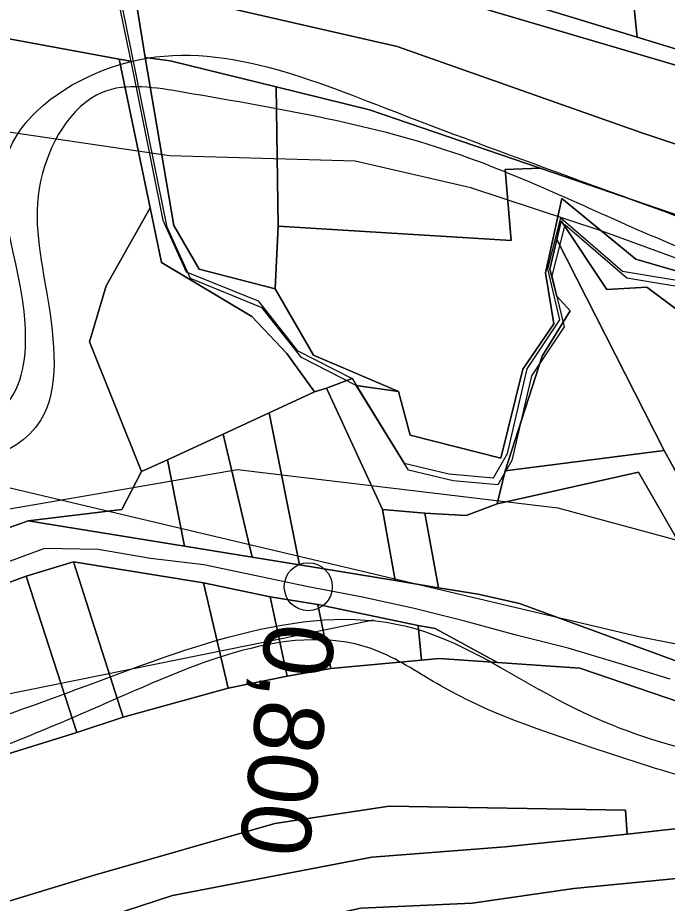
# Model space of a CAD drawing. Extents: x -510989 to -501240, y -1184665 to -1176098.
# Drawn here: x -503968.4 to -503846.8, y -1180716 to -1180550.1 of the extents above; entities that cross this region are included whole.
import ezdxf

# ---------------------------------------------------------------- set-up
doc = ezdxf.new("R2010")
doc.units = 0
for name, color, linetype in [('NAVRH_revitalizace_toku', 7, 'Continuous'), ('ostatni_plocha_x_draha', 7, 'Continuous'), ('ostatni_plocha_x_ostatni_komunikace', 7, 'Continuous'), ('ostatni_plocha_x_silnice', 7, 'Continuous'), ('popis', 7, 'Continuous'), ('STAV_zaplavove_uzemi', 7, 'Continuous'), ('trasovani_toku', 7, 'Continuous'), ('trvaly_travni_porost', 7, 'Continuous'), ('vodni_plocha_x_vodni_tok_v_koryt_prir_n_upr', 7, 'Continuous'), ('vrstevnice_02', 7, 'Continuous')]:
    doc.layers.add(name, color=color, linetype=linetype)

msp = doc.modelspace()

# ---------------------------------------------------------------- linework, layer by layer
at = {"layer": 'NAVRH_revitalizace_toku'}
for points in [[(-503969.95, -1180642.09), (-503927.27, -1180634.75), (-503867.26, -1180641.91), (-503821.69, -1180654.25), (-503752.11, -1180673.74)], [(-503901.78, -1180662.94), (-503999.13, -1180682.69), (-504068.01, -1180696.67), (-504089.48, -1180705.16), (-504129.41, -1180745.09), (-504183.13, -1180792.56)]]:
    msp.add_lwpolyline(points, dxfattribs=at)
at = {"layer": 'ostatni_plocha_x_draha'}
for points in [[(-504050.38, -1180529.2), (-504011.3, -1180526.7), (-503991.91, -1180525.26), (-503972.65, -1180526.94), (-503942.7, -1180531.97), (-503920.4, -1180536.44), (-503878.69, -1180549.11), (-503842.28, -1180559.88), (-503797.62, -1180573.3), (-503768.92, -1180582.78), (-503755.03, -1180588.3), (-503740.5, -1180595.42), (-503728.04, -1180603.41), (-503696.54, -1180625.52), (-503684.47, -1180634.75), (-503671.84, -1180646.84), (-503660.86, -1180660.05), (-503645.78, -1180680.44), (-503636.8, -1180694.49), (-503624.93, -1180717.25)], [(-503536.64, -1180850.18), (-503560.57, -1180820.77), (-503579.71, -1180795.62), (-503597.29, -1180777.84), (-503641.82, -1180728.5), (-503675.8, -1180687.66), (-503699.02, -1180661.49), (-503714.51, -1180645.55), (-503771.73, -1180604.31), (-503793.07, -1180592.97), (-503820.15, -1180582.16), (-503851.54, -1180571.67), (-503897.34, -1180555.49), (-503936.67, -1180546.45), (-503962.9, -1180542.96), (-503983.6, -1180531.11), (-503992.96, -1180529.75), (-504016.96, -1180533.2), (-504032.06, -1180536.14), (-504051.35, -1180540.4)], [(-504050.53, -1180715.17), (-503994.39, -1180690.6), (-503992.99, -1180695.12), (-503985.88, -1180692.95), (-503973.84, -1180689.11), (-503957.35, -1180683.97), (-503948.66, -1180681.12), (-503928.99, -1180675.68), (-503917.92, -1180673.46), (-503909.8, -1180672), (-503892.82, -1180670.42), (-503889.47, -1180670.16), (-503878.59, -1180670.9), (-503863.19, -1180671.95), (-503822.35, -1180685.85), (-503787.22, -1180684.15), (-503784.06, -1180691.38), (-503775.83, -1180695.17), (-503729.09, -1180703.71), (-503708.13, -1180713.81), (-503705.69, -1180714.15), (-503707.85, -1180720.08)], [(-503734.33, -1180721.65), (-503751.58, -1180714.96), (-503794.99, -1180714.3), (-503808.49, -1180705.28), (-503817.5, -1180698.91), (-503854.29, -1180703), (-503854.59, -1180698.53), (-503898.88, -1180697.77), (-503920.25, -1180701.03), (-503954.25, -1180710.8), (-503989.35, -1180721.46)]]:
    msp.add_lwpolyline(points, dxfattribs=at)
at = {"layer": 'ostatni_plocha_x_ostatni_komunikace'}
for points in [[(-504051.14, -1180525.96), (-504032.16, -1180524.67), (-504012.08, -1180523.31), (-503992.58, -1180522.08), (-503984.03, -1180522.66), (-503971.77, -1180523.59), (-503964.41, -1180524.89), (-503942.14, -1180528.82), (-503919.43, -1180533.57), (-503877.43, -1180546.1), (-503852.44, -1180553.76), (-503841.4, -1180557.14), (-503807.92, -1180566.86), (-503796.47, -1180570.18), (-503772.8, -1180577.92), (-503767.53, -1180579.65), (-503754.07, -1180585.16), (-503744.07, -1180590.17), (-503738.37, -1180593.05), (-503724.98, -1180601.86)], [(-503624.93, -1180717.25), (-503636.8, -1180694.49), (-503645.78, -1180680.44), (-503660.86, -1180660.05), (-503671.84, -1180646.84), (-503684.47, -1180634.75), (-503696.54, -1180625.52), (-503728.04, -1180603.41), (-503740.5, -1180595.42), (-503755.03, -1180588.3), (-503768.92, -1180582.78), (-503797.62, -1180573.3), (-503842.28, -1180559.88), (-503878.69, -1180549.11), (-503920.4, -1180536.44), (-503942.7, -1180531.97), (-503972.65, -1180526.94), (-503991.91, -1180525.26), (-504011.3, -1180526.7), (-504050.38, -1180529.2)]]:
    msp.add_lwpolyline(points, dxfattribs=at)
at = {"layer": 'ostatni_plocha_x_silnice'}
for points in [[(-504072.24, -1180546.98), (-504010.25, -1180539.68), (-503958.29, -1180544.03), (-503949.49, -1180547.17), (-503947.96, -1180554.73), (-503947.24, -1180558.25), (-503949.39, -1180557.86), (-503956.84, -1180556.49), (-503978.56, -1180552.5), (-503985.02, -1180552.37), (-504002.84, -1180552.02), (-504013.31, -1180551.82), (-504017.65, -1180552.14), (-504049.58, -1180554.46)], [(-503723.72, -1180656.77), (-503750.38, -1180635.24), (-503779.78, -1180615.05), (-503800.58, -1180604.27), (-503827.69, -1180593), (-503835.46, -1180590.34), (-503870.6, -1180578.32), (-503902.52, -1180567.39), (-503920.01, -1180563.08), (-503939.86, -1180558.18), (-503944.5, -1180557.55), (-503945.09, -1180554.04), (-503946.18, -1180547.54), (-503951.51, -1180546.09), (-503962.9, -1180542.96), (-503936.67, -1180546.45), (-503897.34, -1180555.49), (-503851.54, -1180571.67), (-503820.15, -1180582.16), (-503793.07, -1180592.97), (-503771.73, -1180604.31), (-503714.51, -1180645.55)]]:
    msp.add_lwpolyline(points, dxfattribs=at)
at = {"layer": 'popis'}
msp.add_lwpolyline([(-503840.45, -1180601.19), (-503854.39, -1180598.91), (-503865.95, -1180588.91), (-503868.39, -1180598.43), (-503866.08, -1180608.02), (-503872.22, -1180617.17), (-503875.89, -1180633.02), (-503878.53, -1180637.62), (-503886.9, -1180636.85), (-503895.25, -1180634.84), (-503905.01, -1180619), (-503915.26, -1180613.73), (-503922.6, -1180604.43), (-503936.06, -1180598.98), (-503940.41, -1180589.33), (-503948.71, -1180548.45), (-503964.98, -1180543.24), (-503986.95, -1180532.09), (-504014.98, -1180533.71), (-504031.14, -1180537.19), (-504050.39, -1180541.83)], dxfattribs=at)
at = {"layer": 'STAV_zaplavove_uzemi'}
for points in [[(-504540.1, -1180857.4), (-504577.6, -1180869.9), (-504578.56, -1180860.28), (-504550.67, -1180843.94), (-504523.75, -1180837.2), (-504478.55, -1180823.74), (-504444.9, -1180804.51), (-504446.82, -1180793.93), (-504446.82, -1180779.51), (-504445.86, -1180755.47), (-504441.05, -1180745.85), (-504426.63, -1180754.51), (-504417.97, -1180766.04), (-504413.17, -1180777.58), (-504398.74, -1180788.16), (-504367.97, -1180786.24), (-504329.51, -1180770.85), (-504283.35, -1180754.51), (-504262.2, -1180724.7), (-504238.16, -1180694.89), (-504218.92, -1180663.15), (-504185.27, -1180631.42), (-504166.04, -1180606.42), (-504143.92, -1180591.03), (-504113.15, -1180572.76), (-504085.26, -1180570.84), (-504067.95, -1180564.11), (-504042.95, -1180584.3), (-504041.99, -1180609.3), (-504034.29, -1180620.84), (-504019.87, -1180632.38), (-503985.25, -1180627.57), (-503970.83, -1180622.77), (-503966.98, -1180607.38), (-503969.87, -1180574.69), (-503950.64, -1180559.3), (-503899.67, -1180566.99), (-503832.36, -1180592), (-503773.38, -1180619.38), (-503737.54, -1180645.61), (-503699.95, -1180679.7), (-503682.47, -1180704.18), (-503669.35, -1180719.04), (-503664.11, -1180725.16), (-503685.09, -1180722.54), (-503689.46, -1180721.66), (-503691.21, -1180741.77), (-503665.86, -1180776.74), (-503654.49, -1180807.33), (-503622.15, -1180837.93), (-503605.54, -1180857.16), (-503581.94, -1180873.77), (-503569.7, -1180887.76), (-503551.34, -1180899.12), (-503533.86, -1180905.24), (-503519.87, -1180914.86), (-503521.62, -1180886.01), (-503509.38, -1180869.4), (-503486.65, -1180862.41), (-503463.92, -1180863.28), (-503442.94, -1180864.15), (-503421.09, -1180871.15), (-503407.1, -1180879.02), (-503403.6, -1180885.13), (-503432.45, -1180912.23), (-503450.81, -1180934.96), (-503458.68, -1180948.07), (-503460.51, -1180958), (-503445.13, -1180968.57), (-503429.74, -1180958.96), (-503410.51, -1180930.11), (-503389.35, -1180907.03), (-503369.16, -1180886.84), (-503347.04, -1180874.34), (-503333.58, -1180868.57), (-503300.89, -1180867.61), (-503271.08, -1180854.15), (-503218.19, -1180816.64), (-503177.8, -1180772.41), (-503136.45, -1180737.79), (-503127.8, -1180727.21), (-503108.57, -1180722.41), (-503094.14, -1180728.18), (-503074.91, -1180728.18), (-503051.83, -1180714.71), (-503035.48, -1180702.21), (-503022.02, -1180736.83), (-503014.33, -1180767.6), (-503006.64, -1180784.91), (-502997.02, -1180789.72), (-502932.59, -1180779.14)], [(-503691.1, -1180709.63), (-503698.14, -1180689.92), (-503726.29, -1180661.77), (-503758.67, -1180635.02), (-503793.87, -1180613.9), (-503848.78, -1180591.37), (-503885.38, -1180575.88), (-503937.22, -1180564.11), (-503952.58, -1180564.11), (-503964.1, -1180580.75), (-503962.82, -1180602.51), (-503964.1, -1180625.54), (-503990.97, -1180635.78), (-504028.09, -1180635.78), (-504080.57, -1180656.26), (-504118.96, -1180675.46), (-504153.52, -1180702.34), (-504177.84, -1180745.85), (-504193.2, -1180768.89), (-504226.47, -1180789.37), (-504318.63, -1180820.09), (-504383.9, -1180844.41), (-504463.25, -1180867.44), (-504524.69, -1180885.36), (-504582.26, -1180902.78), (-504631.98, -1180942.98), (-504690.15, -1180991.64), (-504735.64, -1181042.41), (-504756.79, -1181076.26), (-504777.95, -1181112.22)], [(-504594.17, -1181642.09), (-504629.77, -1181535.28), (-504650.39, -1181443.46), (-504674.75, -1181355.39), (-504706.6, -1181265.44), (-504719.72, -1181182.99), (-504747.83, -1181113.66), (-504727.29, -1181064.42), (-504683.65, -1181020.77), (-504624.52, -1180967.28), (-504575.24, -1180927.85), (-504544.27, -1180915.18), (-504445.72, -1180881.39), (-504404.89, -1180867.31), (-504292.26, -1180829.3), (-504179.63, -1180791.29), (-504099.38, -1180734.98), (-504020.54, -1180698.37), (-503957.18, -1180675.84), (-503893.83, -1180664.58), (-503865.67, -1180678.66), (-503817.8, -1180689.92), (-503788.24, -1180689.92), (-503764.3, -1180695.55), (-503736.15, -1180687.11), (-503717.85, -1180698.37), (-503716.44, -1180708.23)], [(-502250.32, -1184002.61), (-502355.07, -1183875.41), (-502442.37, -1183790.61), (-502477.29, -1183700.82), (-502532.16, -1183578.61), (-502567.08, -1183448.91), (-502626.05, -1183402.34), (-502705.41, -1183380.59), (-502814.2, -1183349.87), (-502882.03, -1183297.39), (-502931.95, -1183237.24), (-503042.02, -1183107.97), (-503139.64, -1183018.94), (-503222.14, -1182957.59), (-503308.56, -1182839.96), (-503316.24, -1182784.92), (-503330.32, -1182756.77), (-503348.24, -1182719.65), (-503334.16, -1182651.82), (-503323.92, -1182595.5), (-503313.68, -1182526.39), (-503294.1, -1182480.5), (-503251.86, -1182396.03), (-503229.34, -1182314.37), (-503216.1, -1182227.15), (-503242.43, -1182174.5), (-503271.86, -1182129.59), (-503287.34, -1182081.58), (-503343.88, -1182028.1), (-503361.79, -1182008.91), (-503396.35, -1181952.59), (-503442.43, -1181933.39), (-503497.46, -1181888.6), (-503525.62, -1181860.44), (-503528.18, -1181837.4), (-503548.66, -1181767.01), (-503558.9, -1181729.89), (-503576.82, -1181682.53), (-503578.1, -1181621.1), (-503567.86, -1181572.46), (-503552.5, -1181536.63), (-503538.04, -1181458.36), (-503518.33, -1181411.9), (-503509.88, -1181341.51), (-503497.21, -1181207.63), (-503499.77, -1181097.56), (-503498.02, -1181031.35), (-503510.82, -1180970.85), (-503549.22, -1180952.23), (-503571.32, -1180940.6), (-503605.07, -1180937.11), (-503651.61, -1180939.44), (-503671.39, -1180917.33), (-503679.53, -1180892.89), (-503713.27, -1180871.95), (-503727.24, -1180859.15), (-503734.22, -1180833.55), (-503728.4, -1180799.81), (-503741.2, -1180770.72), (-503722.82, -1180725.17), (-503721.54, -1180703.41), (-503731.78, -1180697.01), (-503767.61, -1180699.57), (-503790.65, -1180697.01), (-503817.53, -1180697.01), (-503861.04, -1180686.77), (-503889.2, -1180675.25), (-503900.72, -1180668.85), (-503953.2, -1180679.09), (-503997.99, -1180697.01), (-504063.27, -1180722.61), (-504109.34, -1180749.49), (-504142.62, -1180776.36), (-504177.18, -1180796.84), (-504211.73, -1180817.32), (-504414.98, -1180961.5), (-504472.7, -1180998.11), (-504544.51, -1181068.5), (-504600.82, -1181143.12), (-504621.94, -1181196.62), (-504641.65, -1181267.01), (-504660.25, -1181350.62), (-504634.7, -1181398.32), (-504617.66, -1181447.72), (-504600.62, -1181492.01), (-504587, -1181548.23), (-504592.11, -1181628.29), (-504569.96, -1181682.81), (-504568.26, -1181664.07), (-504554.63, -1181621.48), (-504547.82, -1181597.63)]]:
    msp.add_spline(points, degree=3, dxfattribs=at)
at = {"layer": 'trasovani_toku'}
for p, q in [((-503963.35, -1180649.51), (-503972.74, -1180652.96)), ((-503953.35, -1180649.69), (-503963.35, -1180649.51)), ((-503943.5, -1180651.42), (-503953.35, -1180649.69)), ((-503933.57, -1180652.59), (-503943.5, -1180651.42)), ((-503923.78, -1180654.63), (-503933.57, -1180652.59)), ((-503914, -1180656.68), (-503923.78, -1180654.63)), ((-503904.18, -1180658.57), (-503914, -1180656.68)), ((-503894.41, -1180660.7), (-503904.18, -1180658.57)), ((-503884.7, -1180663.11), (-503894.41, -1180660.7)), ((-503875.06, -1180665.77), (-503884.7, -1180663.11)), ((-503865.36, -1180668.21), (-503875.06, -1180665.77)), ((-503855.78, -1180671.07), (-503865.36, -1180668.21)), ((-503846.23, -1180674.03), (-503855.78, -1180671.07))]:
    msp.add_line(p, q, dxfattribs=at)
msp.add_circle((-503914, -1180656.68), 4.5, dxfattribs=at)
at = {"layer": 'trvaly_travni_porost'}
for points in [[(-503816.01, -1180376.68), (-503812.14, -1180456.03), (-503807.92, -1180566.86), (-503841.4, -1180557.14), (-503852.44, -1180553.76), (-503854.17, -1180536.75), (-503860.36, -1180403.19), (-503861.57, -1180383.19)], [(-503861.57, -1180383.19), (-503860.36, -1180403.19), (-503854.17, -1180536.75), (-503852.44, -1180553.76), (-503877.43, -1180546.1), (-503919.43, -1180533.57), (-503942.14, -1180528.82), (-503964.41, -1180524.89), (-503961.55, -1180459.33), (-503944.83, -1180447.03), (-503932.5, -1180383.57), (-503923.37, -1180385.97), (-503919.18, -1180385.93), (-503874.64, -1180385.39)], [(-503985.02, -1180552.37), (-503978.56, -1180552.5), (-503956.84, -1180556.49), (-503949.39, -1180557.86), (-503943.59, -1180585.71), (-503951.8, -1180600.31), (-503954.95, -1180610.82), (-503945.2, -1180635.13), (-503948.91, -1180642.22), (-503966.4, -1180644.35), (-503996.74, -1180655.12), (-504002.46, -1180626.97), (-503974.61, -1180623.65), (-503970, -1180617.17), (-503971.76, -1180602.39), (-503975.81, -1180568.47), (-503990.36, -1180570.2), (-503991.29, -1180561.34), (-503988.19, -1180554.21)], [(-503944.5, -1180557.55), (-503939.86, -1180558.18), (-503920.01, -1180563.08), (-503919.66, -1180589.14), (-503920.21, -1180600.91), (-503934.45, -1180597.21), (-503939.18, -1180589.02)], [(-503920.01, -1180563.08), (-503902.52, -1180567.39), (-503870.6, -1180578.32), (-503877.13, -1180578.51), (-503876.03, -1180591.81), (-503919.66, -1180589.14)], [(-503877.13, -1180578.51), (-503870.6, -1180578.32), (-503835.46, -1180590.34), (-503835.77, -1180600.25), (-503852.67, -1180595.35), (-503866.55, -1180583.97), (-503869.62, -1180597.91), (-503868.01, -1180607.45), (-503873.83, -1180615.96), (-503877.97, -1180632.59), (-503894.93, -1180628.28), (-503897.09, -1180620.09), (-503913, -1180613.29), (-503920.21, -1180600.91), (-503919.66, -1180589.14), (-503876.03, -1180591.81)], [(-503941.46, -1180595.95), (-503924.53, -1180606.05), (-503918.04, -1180613.02), (-503912.84, -1180620.2), (-503921.33, -1180624.12), (-503929.95, -1180628.09), (-503940.35, -1180632.89), (-503945.2, -1180635.13), (-503954.95, -1180610.82), (-503951.8, -1180600.31), (-503943.59, -1180585.71)], [(-503866.63, -1180588.13), (-503858.09, -1180601.01), (-503850.61, -1180600.55), (-503844.7, -1180605.02), (-503844.77, -1180611.52), (-503836.23, -1180617.77), (-503830.46, -1180627.98), (-503835.88, -1180634.76), (-503828.82, -1180646.25), (-503821.97, -1180662.15), (-503830.28, -1180662.27), (-503847.36, -1180631.19), (-503867.47, -1180591.65)], [(-503867.47, -1180591.65), (-503847.36, -1180631.19), (-503877.17, -1180635), (-503870.24, -1180613.5), (-503864.98, -1180605.02), (-503867.48, -1180602.26), (-503868.79, -1180597.2)], [(-503910.61, -1180619.47), (-503900.1, -1180642.21), (-503897.72, -1180655.49), (-503915.64, -1180652.58), (-503921.33, -1180624.12), (-503912.84, -1180620.2)], [(-503921.33, -1180624.12), (-503915.64, -1180652.58), (-503924.5, -1180651.15), (-503929.95, -1180628.09)], [(-503929.95, -1180628.09), (-503924.5, -1180651.15), (-503937.15, -1180649.09), (-503940.35, -1180632.89)], [(-503877.17, -1180635), (-503847.36, -1180631.19), (-503830.28, -1180662.27), (-503822.79, -1180667.33), (-503806.5, -1180672.2), (-503786.19, -1180674.61), (-503786.48, -1180677.26), (-503821.66, -1180679.28), (-503834.36, -1180674.54), (-503836.06, -1180663.26), (-503852.2, -1180635.23), (-503878.62, -1180641.18)], [(-503940.35, -1180632.89), (-503937.15, -1180649.09), (-503966.4, -1180644.35), (-503948.91, -1180642.22), (-503945.2, -1180635.13)], [(-503852.2, -1180635.23), (-503836.06, -1180663.26), (-503834.36, -1180674.54), (-503874.46, -1180659.82), (-503882.22, -1180658.11), (-503889.6, -1180656.92), (-503892.15, -1180642.93), (-503884.47, -1180643.32), (-503878.62, -1180641.18)], [(-503892.15, -1180642.93), (-503889.6, -1180656.92), (-503897.72, -1180655.49), (-503900.1, -1180642.21)], [(-503957.97, -1180652.04), (-503948.66, -1180681.12), (-503957.35, -1180683.97), (-503966.82, -1180654.69)], [(-503933.58, -1180655.96), (-503928.99, -1180675.68), (-503948.66, -1180681.12), (-503957.97, -1180652.04)], [(-503984.13, -1180661.1), (-503966.82, -1180654.69), (-503957.35, -1180683.97), (-503973.84, -1180689.11)], [(-503921.14, -1180658.56), (-503917.92, -1180673.46), (-503928.99, -1180675.68), (-503933.58, -1180655.96)], [(-503912.2, -1180660.02), (-503909.8, -1180672), (-503917.92, -1180673.46), (-503921.14, -1180658.56)], [(-503893.45, -1180663.95), (-503892.82, -1180670.42), (-503909.8, -1180672), (-503912.2, -1180660.02)], [(-503893.45, -1180663.95), (-503890.23, -1180664.52), (-503878.59, -1180670.9), (-503889.47, -1180670.16), (-503892.82, -1180670.42)]]:
    msp.add_lwpolyline(points, close=True, dxfattribs=at)
for points in [[(-504051.42, -1180752.99), (-504025.85, -1180738.05), (-503989.35, -1180721.46), (-503954.25, -1180710.8), (-503920.25, -1180701.03), (-503898.88, -1180697.77), (-503854.59, -1180698.53), (-503854.29, -1180703), (-503877.16, -1180705.4), (-503902.1, -1180707.33), (-503939.39, -1180714.5), (-503975.8, -1180726.36), (-504011.5, -1180742.64), (-504043.63, -1180761.77)], [(-504043.63, -1180761.77), (-504011.5, -1180742.64), (-503975.8, -1180726.36), (-503939.39, -1180714.5), (-503902.1, -1180707.33), (-503877.16, -1180705.4), (-503854.29, -1180703), (-503817.5, -1180698.91), (-503808.49, -1180705.28), (-503839.35, -1180710.77), (-503864.26, -1180713.18), (-503883.3, -1180715.93), (-503904.17, -1180716.89), (-503942.31, -1180725.3), (-503977.3, -1180737.63), (-504004.99, -1180751.36), (-504042.72, -1180773.54)], [(-504042.72, -1180773.54), (-504004.99, -1180751.36), (-503977.3, -1180737.63), (-503942.31, -1180725.3), (-503904.17, -1180716.89), (-503883.3, -1180715.93), (-503864.26, -1180713.18), (-503839.35, -1180710.77), (-503808.49, -1180705.28), (-503794.99, -1180714.3), (-503837.47, -1180721.93), (-503874.52, -1180727.1), (-503902.61, -1180728.83), (-503932.95, -1180734.75), (-503973.31, -1180747.67), (-504005.62, -1180763.69), (-504037.66, -1180782.1)]]:
    msp.add_lwpolyline(points, dxfattribs=at)
at = {"layer": 'vodni_plocha_x_vodni_tok_v_koryt_prir_n_upr'}
for points in [[(-503946.18, -1180547.54), (-503945.09, -1180554.04), (-503944.5, -1180557.55), (-503939.18, -1180589.02), (-503934.45, -1180597.21), (-503920.21, -1180600.91), (-503913, -1180613.29), (-503897.09, -1180620.09), (-503905.01, -1180619), (-503915.26, -1180613.73), (-503922.6, -1180604.43), (-503936.06, -1180598.98), (-503940.41, -1180589.33), (-503948.71, -1180548.45)], [(-503840.45, -1180601.19), (-503854.39, -1180598.91), (-503865.95, -1180588.91), (-503868.39, -1180598.43), (-503866.08, -1180608.02), (-503872.22, -1180617.17), (-503875.89, -1180633.02), (-503878.53, -1180637.62), (-503886.9, -1180636.85), (-503895.25, -1180634.84), (-503905.01, -1180619), (-503897.09, -1180620.09), (-503894.93, -1180628.28), (-503877.97, -1180632.59), (-503873.83, -1180615.96), (-503868.01, -1180607.45), (-503869.62, -1180597.91), (-503866.55, -1180583.97), (-503852.67, -1180595.35), (-503835.77, -1180600.25)], [(-503844.7, -1180605.02), (-503850.61, -1180600.55), (-503858.09, -1180601.01), (-503866.63, -1180588.13), (-503867.47, -1180591.65), (-503868.79, -1180597.2), (-503867.48, -1180602.26), (-503864.98, -1180605.02), (-503870.24, -1180613.5), (-503877.17, -1180635), (-503878.62, -1180641.18), (-503884.47, -1180643.32), (-503892.15, -1180642.93), (-503900.1, -1180642.21), (-503910.61, -1180619.47), (-503905.8, -1180617.7), (-503896.05, -1180633.53), (-503887.7, -1180635.53), (-503879.33, -1180636.3), (-503876.69, -1180631.71), (-503873.01, -1180615.86), (-503866.88, -1180606.72), (-503869.18, -1180597.13), (-503866.74, -1180587.62), (-503855.18, -1180597.61), (-503841.24, -1180599.89)], [(-504039.68, -1180665.84), (-504031.52, -1180663.79), (-504017.4, -1180661.74), (-504005.8, -1180658.28), (-503996.74, -1180655.12), (-503966.4, -1180644.35), (-503937.15, -1180649.09), (-503924.5, -1180651.15), (-503915.64, -1180652.58), (-503897.72, -1180655.49), (-503889.6, -1180656.92), (-503882.22, -1180658.11), (-503874.46, -1180659.82), (-503834.36, -1180674.54)], [(-503822.35, -1180685.85), (-503863.19, -1180671.95), (-503878.59, -1180670.9), (-503890.23, -1180664.52), (-503893.45, -1180663.95), (-503912.2, -1180660.02), (-503921.14, -1180658.56), (-503933.58, -1180655.96), (-503957.97, -1180652.04), (-503966.82, -1180654.69), (-503984.13, -1180661.1), (-503993.69, -1180664.7), (-504001.67, -1180667.54), (-504074.25, -1180680.65)]]:
    msp.add_lwpolyline(points, dxfattribs=at)
msp.add_lwpolyline([(-503949.39, -1180557.86), (-503947.24, -1180558.25), (-503941.2, -1180588.03), (-503936.85, -1180597.68), (-503923.4, -1180603.13), (-503916.05, -1180612.43), (-503905.8, -1180617.7), (-503910.61, -1180619.47), (-503912.84, -1180620.2), (-503918.04, -1180613.02), (-503924.53, -1180606.05), (-503941.46, -1180595.95), (-503943.59, -1180585.71)], close=True, dxfattribs=at)
at = {"layer": 'vrstevnice_02'}
for points in [[(-503730.41, -1180581), (-503750.81, -1180583), (-503789.59, -1180572), (-503800, -1180572), (-503807.41, -1180577), (-503806.81, -1180595), (-503812.41, -1180606), (-503815.5, -1180606), (-503859.19, -1180590), (-503883.59, -1180582), (-503905.19, -1180577), (-503940, -1180576), (-503974, -1180571), (-503987.31, -1180571), (-503997.41, -1180576), (-504020.91, -1180591), (-504031.5, -1180595), (-504057.41, -1180600)], [(-504055.09, -1180651), (-503994.81, -1180635), (-503983.31, -1180635), (-503852.09, -1180666), (-503795.91, -1180677), (-503768.81, -1180693), (-503746.91, -1180722)]]:
    msp.add_lwpolyline(points, dxfattribs=at)

# ---------------------------------------------------------------- texts
at = {"layer": 'trasovani_toku'}
msp.add_text('0,800', height=13, rotation=263.0916, dxfattribs=at).set_placement((-503921.74, -1180663.02))

doc.saveas('drawing.dxf')
